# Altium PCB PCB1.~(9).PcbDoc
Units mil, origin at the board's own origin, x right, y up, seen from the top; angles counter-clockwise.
Board outline 3715 x 2925 mil, 2 copper layers (Top Layer, Bottom Layer); 4 components, 38 nets, 176 pads, 0 vias.
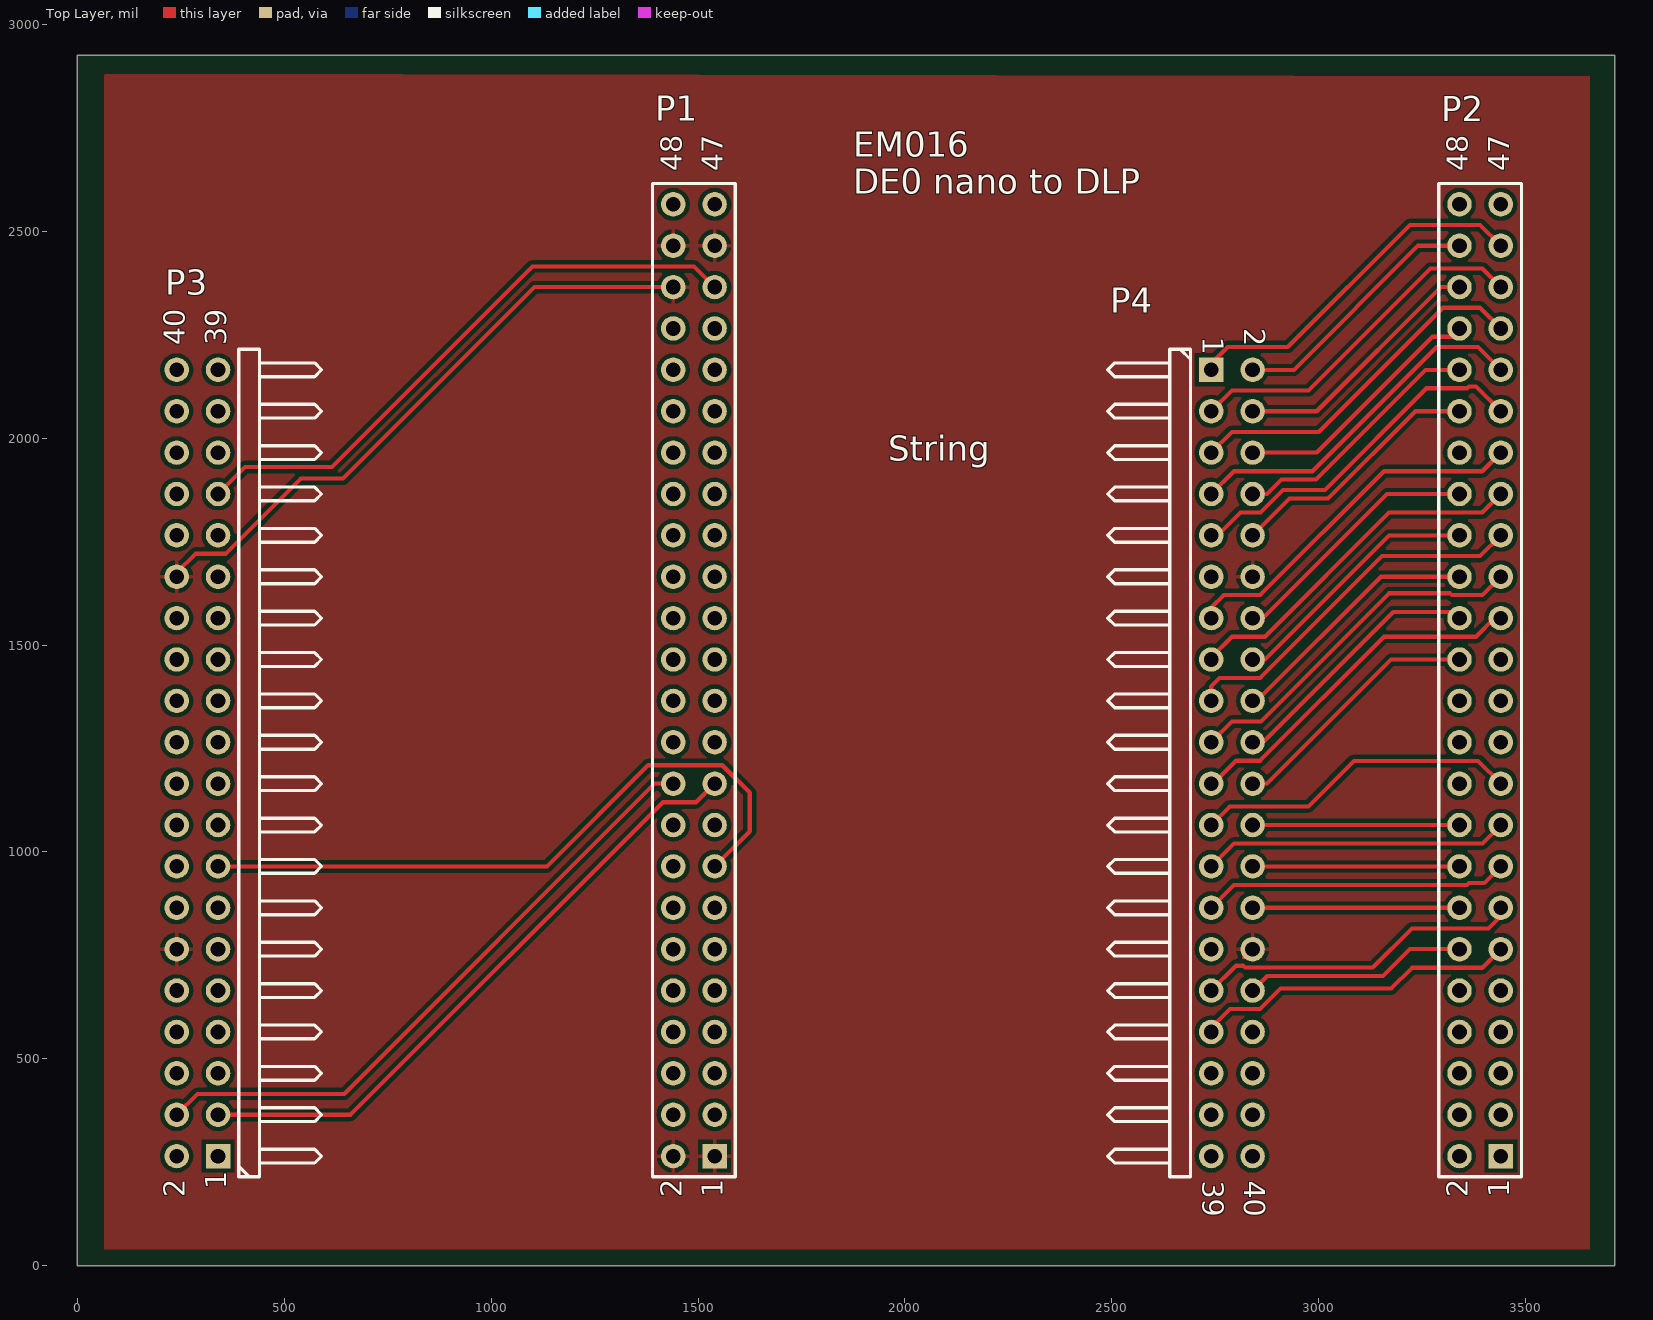
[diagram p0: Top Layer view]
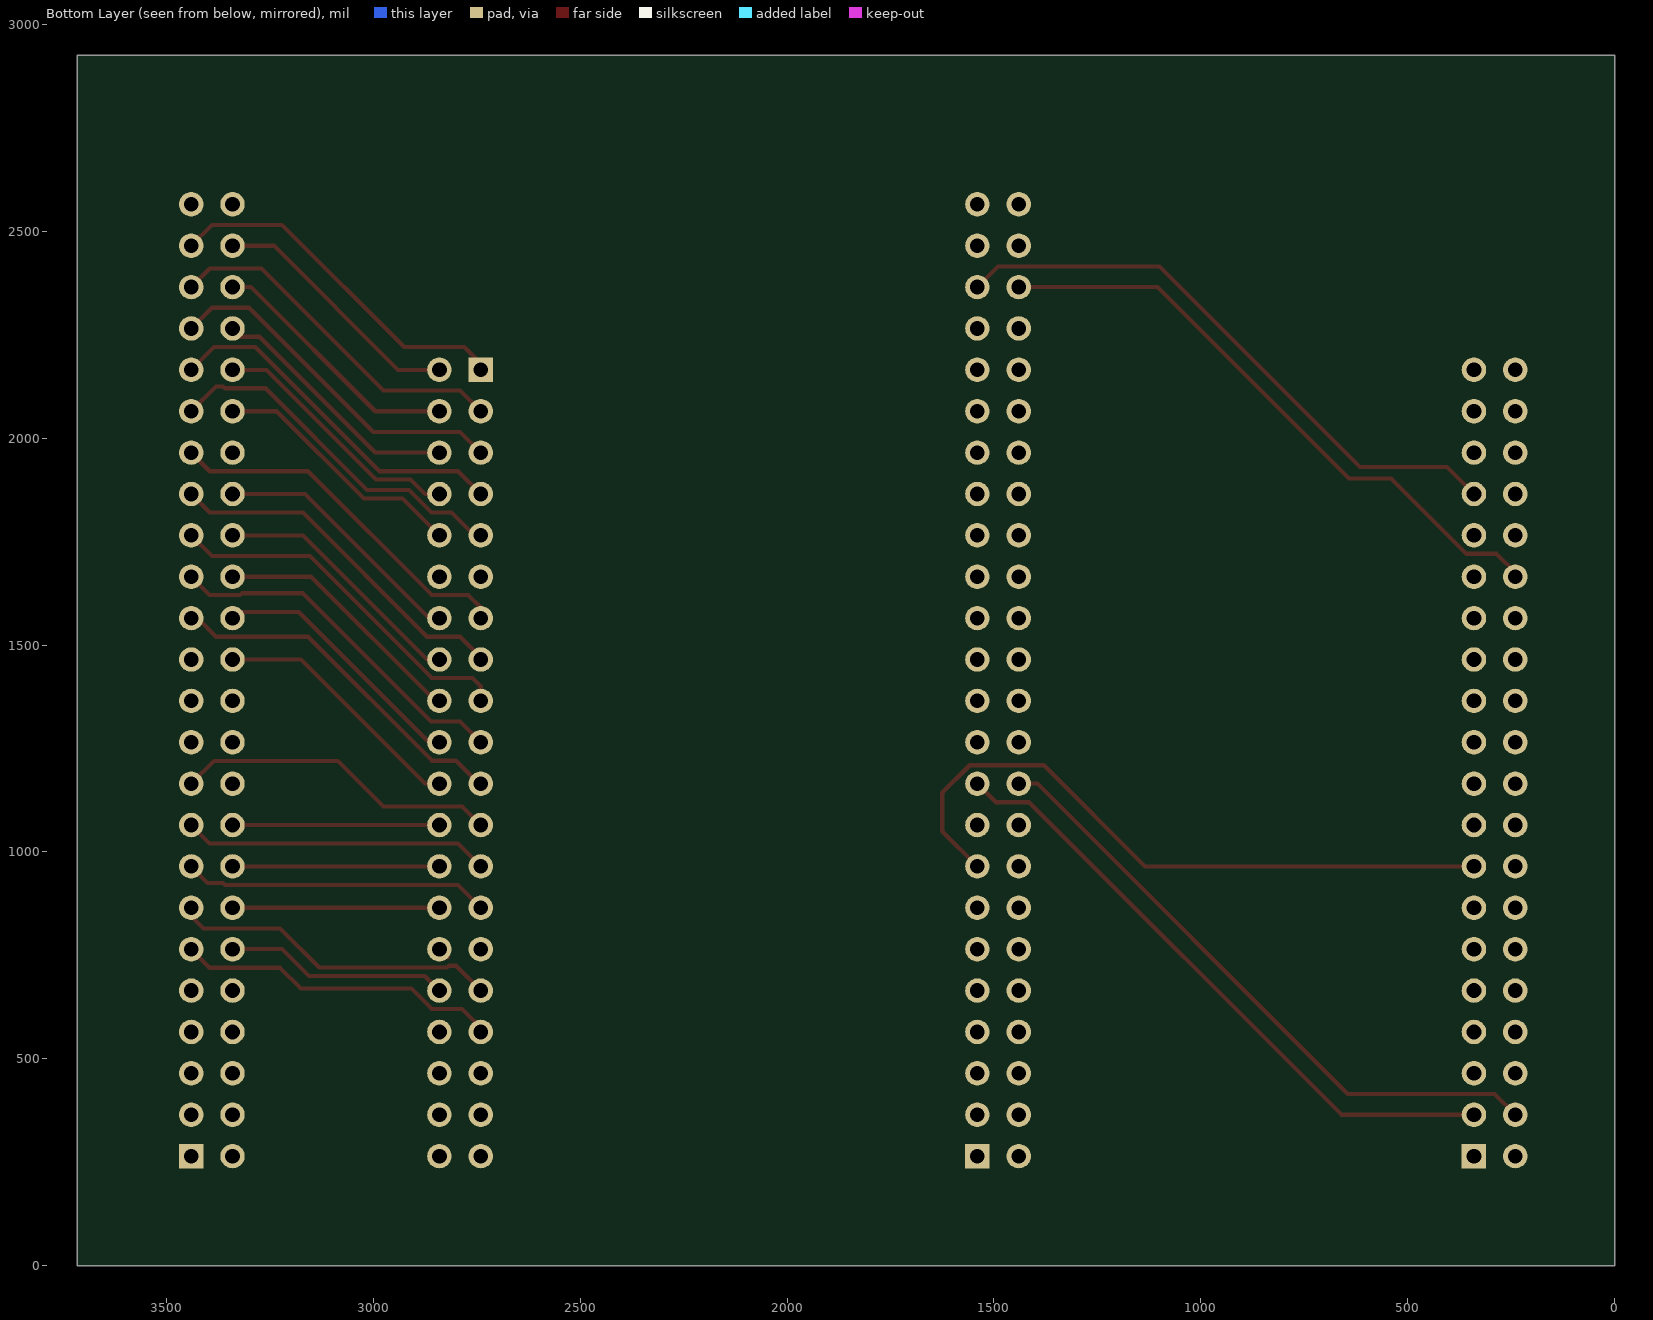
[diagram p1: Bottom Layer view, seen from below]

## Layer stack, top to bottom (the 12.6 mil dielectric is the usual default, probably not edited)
Top Solder: solder mask 0.4, Solder Resist, Dk 3.5
Top Layer: signal copper 1.4
Dielectric 1: dielectric 12.6, FR-4, Dk 4.8
Bottom Layer: signal copper 1.4
Bottom Solder: solder mask 0.4, Solder Resist, Dk 3.5

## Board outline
0,0 3715,0 3715,2925 0,2925

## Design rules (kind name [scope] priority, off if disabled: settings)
Clearance [All] p1: gap=10
PolygonConnect [All] p1: connectstyle=Relief reliefconductorwidth=10 reliefentries=4 polygonreliefangle="90 Angle" airgapwidth=10
RoomDefinition Sheet1 [InComponentClass('Sheet1')] p1 off: confinementstyle=ConfineIn formatcopy=TRUE lockcomponents=FALSE outline 6015,-870 7380,-870 7380,1825 6015,1825
RoutingVias [All] p1: holewidth=28 width=50 viastyle="Through Hole" minholewidth=28 minwidth=50 maxholewidth=28 maxwidth=50
SolderMaskExpansion [All] p1: expansion=4
Width [All] p1: maxlimit=10 minlimit=10 preferedwidth=10
30 further rules are at their usual default settings.

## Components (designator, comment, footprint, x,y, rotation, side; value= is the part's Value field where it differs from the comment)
P1 "Header 24X2" HDR2X24 1540,265 r90 top
P2 "Header 24X2" HDR2X24 3440,265 r90 top
P3 "Header 20X2H" HDR2X20H 340,265 r90 top
P4 "Header 20X2H" HDR2X20H 2740,2165 r270 top

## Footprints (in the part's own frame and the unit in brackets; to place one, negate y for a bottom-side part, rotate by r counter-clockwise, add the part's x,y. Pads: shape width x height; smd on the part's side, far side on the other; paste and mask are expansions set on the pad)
HDR2X20H [mm] "Connector; Header; 20x2 Position; Right Angle"
  rect 1.5x1.5 hole 0.9: 1(0,0)
  round 1.5 hole 0.9: 2(0,2.54) 3(2.54,0) 4(2.54,2.54) 5(5.08,0) 6(5.08,2.54) 7(7.62,0) 8(7.62,2.54) 9(10.16,0) 10(10.16,2.54) 11(12.7,0) 12(12.7,2.54) 13(15.24,0) 14(15.24,2.54) 15(17.78,0) 16(17.78,2.54) 17(20.32,0) 18(20.32,2.54) 19(22.86,0) 20(22.86,2.54) 21(25.4,0) 22(25.4,2.54) 23(27.94,0) 24(27.94,2.54) 25(30.48,0) 26(30.48,2.54) 27(33.02,0) 28(33.02,2.54) 29(35.56,0) 30(35.56,2.54) 31(38.1,0) 32(38.1,2.54) 33(40.64,0) 34(40.64,2.54) 35(43.18,0) 36(43.18,2.54) 37(45.72,0) 38(45.72,2.54) 39(48.26,0) 40(48.26,2.54)
  silkscreen extent -1.27,-6.35 49.53,-1.27
HDR2X24 [mm] "Connector; Header; 24x2 Position"
  rect 1.5x1.5 hole 0.9: 1(0,0)
  round 1.5 hole 0.9: 2(0,2.54) 3(2.54,0) 4(2.54,2.54) 5(5.08,0) 6(5.08,2.54) 7(7.62,0) 8(7.62,2.54) 9(10.16,0) 10(10.16,2.54) 11(12.7,0) 12(12.7,2.54) 13(15.24,0) 14(15.24,2.54) 15(17.78,0) 16(17.78,2.54) 17(20.32,0) 18(20.32,2.54) 19(22.86,0) 20(22.86,2.54) 21(25.4,0) 22(25.4,2.54) 23(27.94,0) 24(27.94,2.54) 25(30.48,0) 26(30.48,2.54) 27(33.02,0) 28(33.02,2.54) 29(35.56,0) 30(35.56,2.54) 31(38.1,0) 32(38.1,2.54) 33(40.64,0) 34(40.64,2.54) 35(43.18,0) 36(43.18,2.54) 37(45.72,0) 38(45.72,2.54) 39(48.26,0) 40(48.26,2.54) 41(50.8,0) 42(50.8,2.54) 43(53.34,0) 44(53.34,2.54) 45(55.88,0) 46(55.88,2.54) 47(58.42,0) 48(58.42,2.54)
  silkscreen extent -1.27,-1.27 59.69,3.81

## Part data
P1 P2: "Header, 24-Pin, Dual row"
P3 P4: "Header, 20-Pin, Dual row, Right Angle"

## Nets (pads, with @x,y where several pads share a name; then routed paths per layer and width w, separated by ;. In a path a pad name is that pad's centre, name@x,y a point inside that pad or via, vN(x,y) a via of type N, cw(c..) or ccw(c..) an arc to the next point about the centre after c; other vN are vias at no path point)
3.3V: P4.29
5V: P4.11
DATA0: P2.45 P4.1 | length 874.5
  Top Layer w10: P4.1 2740,2180 2780,2220 2925,2220 3220,2515 3390,2515 P2.45
DATA1: P2.46 P4.2 | length 624.3
  Top Layer w10: P4.2 2940,2165 3240,2465 P2.46
DATA2: P2.43 P4.3 | length 861.5
  Top Layer w10: P4.3 2790,2115 2975,2115 3270,2410 3395,2410 P2.43
DATA3: P2.44 P4.4 | length 624.3
  Top Layer w10: P4.4 2995,2065 3295,2365 P2.44
DATA4: P2.41 P4.5 | length 865.7
  Top Layer w10: P4.5 2790,2015 3000,2015 3300,2315 3390,2315 P2.41
DATA5: P2.42 P4.6 | length 624.3
  Top Layer w10: P4.6 2995,1965 3275,2245 3320,2245 P2.42
DATA6: P2.39 P4.7 | length 869.8
  Top Layer w10: P4.7 2795,1920 2985,1920 3285,2220 3385,2220 P2.39
DATA7: P2.40 P4.8 | length 624.3
  Top Layer w10: P4.8 2875,1865 2910,1900 2993.28,1900 3258.28,2165 P2.40
DATA8: P2.37 P4.9 | length 874
  Top Layer w10: P4.9 2755,1765 2810.47,1820.47 2858.76,1820.47 2913.28,1875 3015,1875 3260.47,2120.47 3358.44,2120.47 3362.97,2125 3380,2125 P2.37
DATA9: P2.38 P4.10 | length 624.3
  Top Layer w10: P4.10 2929.22,1854.22 3022.5,1854.22 3233.28,2065 P2.38
DATA10: P2.36
DATA11: P2.34 P4.14 | length 624.3
  Top Layer w10: P4.14 2865,1565 3165,1865 P2.34
DATA12: P2.35 P4.13 | length 880.3
  Top Layer w10: P4.13 2740,1590 2770.47,1620.47 2858.44,1620.47 3157.97,1920 3395,1920 P2.35
DATA13: P2.33 P4.15 | length 868.6
  Top Layer w10: P4.15 2740,1470 2790,1520 2870,1520 3170,1820 3395,1820 P2.33
DATA14: P2.31 P4.17 | length 886.2
  Top Layer w10: P4.17 2740,1400 2760.47,1420.47 2858.44,1420.47 3152.97,1715 3390,1715 P2.31
DATA15: P2.32 P4.16 | length 624.3
  Top Layer w10: P4.16 2870,1465 3170,1765 P2.32
DATA16: P2.15 P4.27 | length 741.4
  Top Layer w10: P4.27 2795.47,920.47 3358.44,920.47 3362.97,925 3400,925 P2.15
DATA17: P2.16 P4.26 | length 500
  Top Layer w10: P4.26 P2.16
DATA18: P2.11 P4.33 | length 788.7
  Top Layer w10: P4.33 2740,575 2785.47,620.47 2858.44,620.47 2907.97,670 3175,670 3225,720 3395,720 P2.11
DATA19: P2.12 P4.32 | length 541.4
  Top Layer w10: P4.32 2875.47,700.47 3155.47,700.47 3220,765 P2.12
DATA20: P2.17 P4.25 | length 741.4
  Top Layer w10: P4.25 2795.47,1020.47 3395.47,1020.47 P2.17
DATA21: P2.14 P4.28 | length 500
  Top Layer w10: P4.28 P2.14
DATA22: P2.13 P4.31 | length 798.3
  Top Layer w10: P4.31 2800,725 2817.03,725 2821.56,720.47 3130.47,720.47 3225,815 3410,815 3440,845 P2.13
DATA23: P2.19 P4.23 | length 787
  Top Layer w10: P4.23 2785,1110 2975,1110 3085,1220 3385,1220 P2.19
DATAEN: P2.30 P4.18 | length 624.3
  Top Layer w10: P4.18 2850,1365 3150,1665 P2.30
EXT_SCL: P1.19 P3.3 | length 1531.4
  Top Layer w10: P3.3 660,365 1415,1120 1495,1120 P1.19
EXT_SDA: P1.20 P3.4 | length 1531.4
  Top Layer w10: P3.4 290,415 645,415 1395,1165 P1.20
GND: P1.1 P1.2 P1.44 P1.45 P1.46 P3.12 P3.30 P4.12 P4.30 | length 1524.1
  Top Layer w10: P3.30 240,1675 285.47,1720.47 358.44,1720.47 540,1902.03 642.03,1902.03 1105,2365 P1.44 ; P4.30@2820,745 P4.30
GPIO5: P2.18 P4.24 | length 500
  Top Layer w10: P4.24 P2.18
GPIO_INIT_DONE: P2.26 P4.22 | length 624.3
  Top Layer w10: P4.22 2875,1165 3175,1465 P2.26
HOST_PRESENTZ: P1.43 P3.33 | length 1448.5
  Top Layer w10: P3.33 405,1930 615,1930 1100,2415 1490,2415 P1.43
HSYNC: P2.29 P4.19 | length 869.4
  Top Layer w10: P4.19 2790,1315 2860,1315 3170,1625 3317.03,1625 3321.56,1620.47 3395.47,1620.47 P2.29
PCLK: P2.28 P4.20 | length 636.7
  Top Layer w10: P4.20 2865,1265 3180,1580 3325,1580 P2.28
PROJ_ON_EXT: P1.15 P3.15 | length 1627
  Top Layer w10: P3.15 1135,965 1379.53,1209.53 1558.44,1209.53 1625,1142.97 1625,1050 P1.15
VINTF: P1.3
VSYNC: P2.27 P4.21 | length 865.7
  Top Layer w10: P4.21 2745,1165 2800.47,1220.47 2858.44,1220.47 3157.97,1520 3380,1520 3425,1565 P2.27
pads on no net: P1.4 P1.5 P1.6 P1.7 P1.8 P1.9 P1.10 P1.11 P1.12 P1.13 P1.14 P1.16 P1.17 P1.18 P1.21 P1.22 P1.23 P1.24 P1.25 P1.26 P1.27 P1.28 P1.29 P1.30 P1.31 P1.32 P1.33 P1.34 P1.35 P1.36 P1.37 P1.38 P1.39 P1.40 P1.41 P1.42 P1.47 P1.48 P2.1 P2.2 P2.3 P2.4 P2.5 P2.6 P2.7 P2.8 P2.9 P2.10 P2.20 P2.21 P2.22 P2.23 P2.24 P2.25 P2.47 P2.48 P3.1 P3.2 P3.5 P3.6 P3.7 P3.8 P3.9 P3.10 P3.11 P3.13 P3.14 P3.16 P3.17 P3.18 P3.19 P3.20 P3.21 P3.22 P3.23 P3.24 P3.25 P3.26 P3.27 P3.28 P3.29 P3.31 P3.32 P3.34 P3.35 P3.36 P3.37 P3.38 P3.39 P3.40 P4.34 P4.35 P4.36 P4.37 P4.38 P4.39 P4.40

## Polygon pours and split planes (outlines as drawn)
GND on Top Layer "GND top layer" (solid, pour order 0): 65,2880 65,40 3650,40 3655,40 3655,2875

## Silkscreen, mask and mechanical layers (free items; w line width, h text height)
Top Overlay:
  text "EM016 / DE0 nano to DLP" at 1875,2590 h60
  text "String" at 1960,1945 h60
